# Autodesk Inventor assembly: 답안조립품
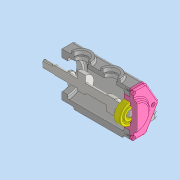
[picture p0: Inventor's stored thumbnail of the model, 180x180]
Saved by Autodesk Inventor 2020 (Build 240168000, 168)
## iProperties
Created: 2021-06
Part Number: 답안조립품
Document SubType Name: Assembly
Designer: PC2-03
Author: PC2-03
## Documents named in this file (5)
- C:\Users\PC2-03\Desktop\710606V1018\답안조립품.iam
- C:\Users\PC2-03\Desktop\710606V1018\본체.ipt
- C:\Users\PC2-03\Desktop\710606V1018\뒷커버.ipt
- C:\Users\PC2-03\Desktop\710606V1018\베어링 6302.ipt
- C:\Users\PC2-03\Desktop\710606V1018\편심축.ipt
